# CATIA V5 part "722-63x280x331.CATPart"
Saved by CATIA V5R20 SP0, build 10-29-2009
Part number: 722-63x280x331
Definition: NONE
Nomenclature: 722-63x280x331
Source: Unknown
Description: 722-63x280x331
Bounding box of the stored display mesh (mm): x -31.5 to 31.5, y -31.5 to 31.5, z -262 to 69
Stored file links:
  C:\Users\Utente\Desktop\IO LAVORO\3D X SITO CF\X SITO\722\722-63x280x331.CATPart
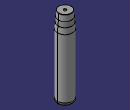
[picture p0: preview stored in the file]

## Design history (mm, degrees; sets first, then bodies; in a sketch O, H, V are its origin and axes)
Body1 "722-63x280x331" (main body)
  Solid1: solid without history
